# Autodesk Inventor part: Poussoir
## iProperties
Shininess: 20.0
Length Units: 11269
Angle Units: 11279
Time Units: 11290
Mass Units: 11283
Length Display Precision: 3
Angle Display Precision: 2
Compacted: True
Created: 2001-06
Part Number: Poussoir
Material: Par défaut
Document SubType Name: Modélisation
Designer: Flavien MARTY
Density: 0.0
Volumn: 0.0
Area: 0.0
PropertySet Name: Model Information
Control State: 0
Master: False
Checked Out: False
Author: Flavien MARTY
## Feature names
1. Extrusion1
2. Congé1 [Fillet]
3. Extrusion2
4. Symétrie1 [Mirror]
5. Perçage1 [Hole]
